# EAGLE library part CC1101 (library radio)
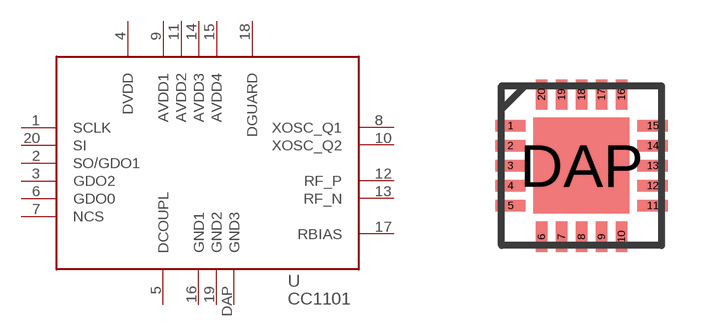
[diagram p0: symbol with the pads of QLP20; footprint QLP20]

Designator prefix U

## CC1101  [QLP20]
1  SCLK
2  SO/GDO1
3  GDO2
4  DVDD
5  DCOUPL
6  GDO0
7  NCS
8  XOSC_Q1
9  AVDD1
10  XOSC_Q2
11  AVDD2
12  RF_P
13  RF_N
14  AVDD3
15  AVDD4
16  GND1
17  RBIAS
18  DGUARD
19  GND2
20  SI
DAP  GND3

## Footprint QLP20 (pad centres in mm)
smd 0.76 x 0.28: 1 -1.78,1; 2 -1.78,0.5; 3 -1.78,0; 4 -1.78,-0.5; 5 -1.78,-1; 11 1.78,-1; 12 1.78,-0.5; 13 1.78,0; 14 1.78,0.5; 15 1.78,1
smd 0.28 x 0.76: 6 -1,-1.78; 7 -0.5,-1.78; 8 0,-1.78; 9 0.5,-1.78; 10 1,-1.78; 16 1,1.78; 17 0.5,1.78; 18 0,1.78; 19 -0.5,1.78; 20 -1,1.78
smd 2.4 x 2.4: DAP 0,0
